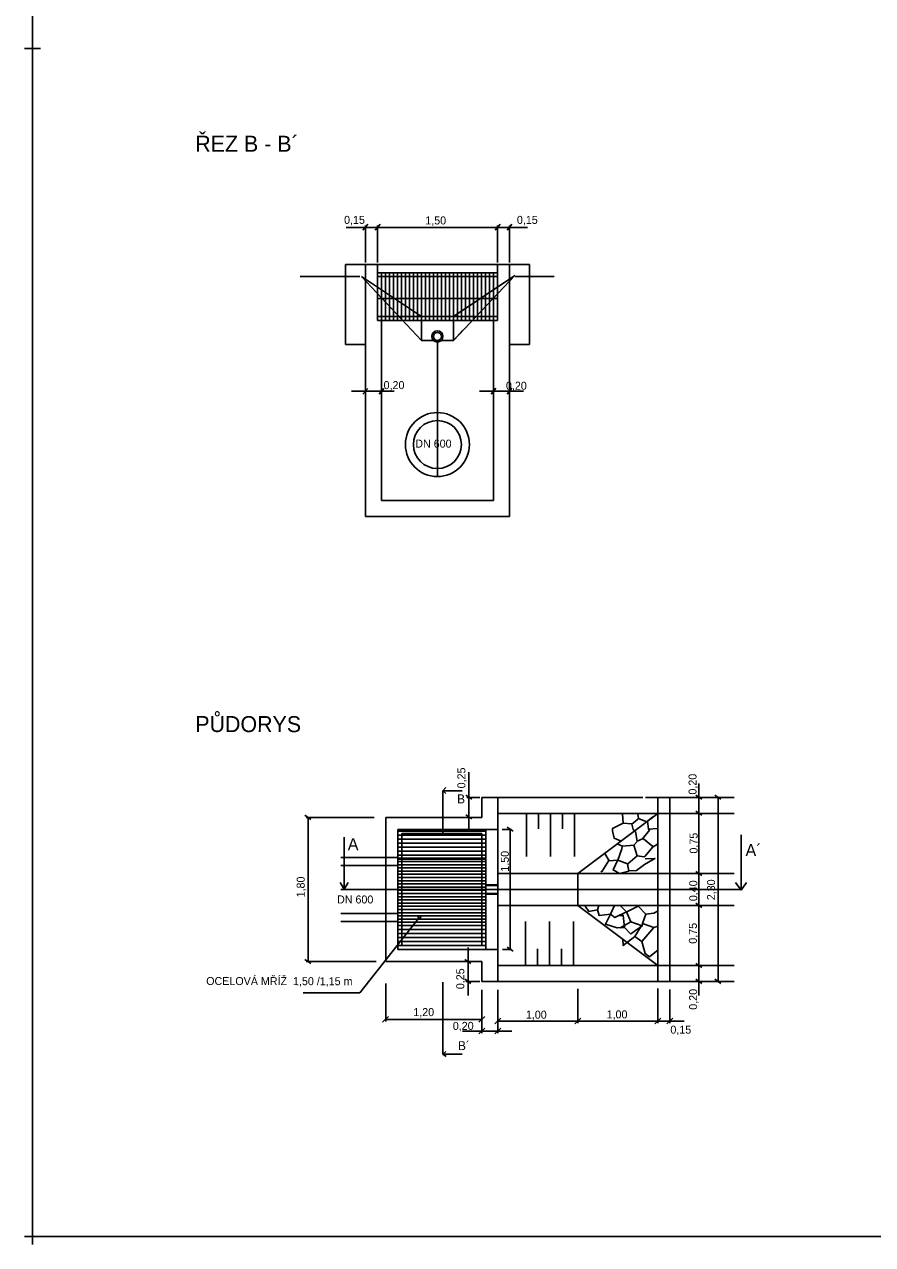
# Model space of a CAD drawing. Extents: x -463166.8 to -463145.6, y -1105023 to -1104993.1.
# Drawn here: x -463166.78 to -463156.18, y -1105022.98 to -1105007.73 of the extents above; entities that cross this region are included whole.
import ezdxf

# ---------------------------------------------------------------- set-up
doc = ezdxf.new("R2010")
doc.units = 0
doc.layers.add('Vrstva 14', color=7, linetype='Continuous')
doc.layers.add('Vrstva 57', color=7, linetype='Continuous')

msp = doc.modelspace()

# ---------------------------------------------------------------- linework, layer by layer
at = {"layer": 'Vrstva 14'}
for p, q in [((-463166.676, -1105007.928), (-463166.676, -1105008.128)), ((-463166.676, -1105007.928), (-463166.676, -1105008.128)), ((-463166.676, -1105007.928), (-463166.676, -1105008.128)), ((-463166.676, -1105007.928), (-463166.676, -1105008.128)), ((-463166.776, -1105008.028), (-463166.576, -1105008.028)), ((-463166.776, -1105008.028), (-463166.576, -1105008.028)), ((-463166.776, -1105008.028), (-463166.576, -1105008.028)), ((-463166.776, -1105008.028), (-463166.576, -1105008.028)), ((-463162.755, -1105010.265), (-463162.363, -1105010.265)), ((-463162.485, -1105010.226), (-463162.545, -1105010.3)), ((-463162.515, -1105010.365), (-463162.515, -1105010.24)), ((-463162.332, -1105010.226), (-463162.392, -1105010.3)), ((-463162.365, -1105010.703), (-463162.365, -1105010.24)), ((-463162.365, -1105010.487), (-463162.365, -1105010.241)), ((-463162.365, -1105010.266), (-463160.865, -1105010.266)), ((-463161.04, -1105010.265), (-463160.487, -1105010.265)), ((-463160.832, -1105010.226), (-463160.892, -1105010.3)), ((-463160.865, -1105010.365), (-463160.865, -1105010.24)), ((-463160.865, -1105010.487), (-463160.865, -1105010.241)), ((-463160.684, -1105010.226), (-463160.744, -1105010.3)), ((-463160.715, -1105010.703), (-463160.715, -1105010.24)), ((-463162.515, -1105010.703), (-463162.515, -1105010.365)), ((-463160.865, -1105010.703), (-463160.865, -1105010.365)), ((-463162.765, -1105010.728), (-463162.765, -1105011.728)), ((-463162.515, -1105010.728), (-463162.765, -1105010.728)), ((-463162.515, -1105010.728), (-463162.365, -1105010.728)), ((-463162.515, -1105010.728), (-463162.515, -1105011.972)), ((-463162.365, -1105010.728), (-463160.865, -1105010.728)), ((-463162.365, -1105010.728), (-463162.365, -1105011.153)), ((-463160.865, -1105010.728), (-463160.715, -1105010.728)), ((-463160.865, -1105010.728), (-463160.865, -1105011.153)), ((-463160.715, -1105010.728), (-463160.465, -1105010.728)), ((-463160.715, -1105010.728), (-463160.715, -1105011.972)), ((-463160.465, -1105010.728), (-463160.465, -1105011.728)), ((-463163.331, -1105010.878), (-463162.583, -1105010.878)), ((-463162.565, -1105010.878), (-463161.828, -1105011.37)), ((-463162.565, -1105010.878), (-463161.815, -1105011.678)), ((-463162.365, -1105010.832), (-463160.865, -1105010.832)), ((-463162.365, -1105011.428), (-463162.365, -1105010.878)), ((-463162.365, -1105010.878), (-463160.865, -1105010.878)), ((-463162.315, -1105011.431), (-463162.315, -1105010.832)), ((-463162.265, -1105011.431), (-463162.265, -1105010.832)), ((-463162.215, -1105011.431), (-463162.215, -1105010.832)), ((-463162.165, -1105011.431), (-463162.165, -1105010.832)), ((-463162.115, -1105011.431), (-463162.115, -1105010.832)), ((-463162.065, -1105011.431), (-463162.065, -1105010.832)), ((-463162.015, -1105011.431), (-463162.015, -1105010.832)), ((-463161.965, -1105011.431), (-463161.965, -1105010.832)), ((-463161.915, -1105011.431), (-463161.915, -1105010.832)), ((-463161.865, -1105011.431), (-463161.865, -1105010.832)), ((-463161.815, -1105011.431), (-463161.815, -1105010.832)), ((-463161.765, -1105011.431), (-463161.765, -1105010.832)), ((-463161.715, -1105011.431), (-463161.715, -1105010.832)), ((-463161.665, -1105011.431), (-463161.665, -1105010.832)), ((-463161.615, -1105011.431), (-463161.615, -1105010.832)), ((-463161.565, -1105011.32), (-463161.565, -1105010.832)), ((-463161.515, -1105011.318), (-463161.515, -1105010.832)), ((-463161.465, -1105011.317), (-463161.465, -1105010.832)), ((-463161.465, -1105011.317), (-463161.465, -1105010.832)), ((-463161.415, -1105011.315), (-463161.415, -1105010.832)), ((-463161.415, -1105011.378), (-463160.648, -1105010.867)), ((-463161.415, -1105011.678), (-463160.648, -1105010.867)), ((-463161.365, -1105011.314), (-463161.365, -1105010.832)), ((-463161.315, -1105011.428), (-463161.315, -1105010.832)), ((-463161.265, -1105011.428), (-463161.265, -1105010.832)), ((-463161.265, -1105011.311), (-463161.265, -1105010.878)), ((-463161.215, -1105011.428), (-463161.215, -1105010.832)), ((-463161.215, -1105011.309), (-463161.215, -1105010.878)), ((-463161.165, -1105011.428), (-463161.165, -1105010.832)), ((-463161.115, -1105011.428), (-463161.115, -1105010.832)), ((-463161.065, -1105011.428), (-463161.065, -1105010.832)), ((-463161.015, -1105011.431), (-463161.015, -1105010.832)), ((-463160.965, -1105011.431), (-463160.965, -1105010.832)), ((-463160.915, -1105011.431), (-463160.915, -1105010.832)), ((-463160.865, -1105011.428), (-463160.865, -1105010.878)), ((-463160.641, -1105010.878), (-463160.157, -1105010.878)), ((-463162.315, -1105011.153), (-463162.365, -1105011.153)), ((-463160.915, -1105011.153), (-463162.365, -1105011.153)), ((-463162.315, -1105011.153), (-463162.315, -1105011.428)), ((-463162.123, -1105011.153), (-463162.315, -1105011.153)), ((-463160.865, -1105011.153), (-463160.915, -1105011.153)), ((-463160.915, -1105011.153), (-463160.915, -1105011.972)), ((-463161.865, -1105011.431), (-463161.865, -1105011.32)), ((-463161.815, -1105011.431), (-463161.815, -1105011.318)), ((-463161.765, -1105011.431), (-463161.765, -1105011.317)), ((-463161.765, -1105011.431), (-463161.765, -1105011.317)), ((-463161.715, -1105011.431), (-463161.715, -1105011.315)), ((-463161.665, -1105011.431), (-463161.665, -1105011.314)), ((-463161.615, -1105011.431), (-463161.615, -1105011.312)), ((-463161.565, -1105011.431), (-463161.565, -1105011.311)), ((-463161.565, -1105011.431), (-463161.565, -1105011.311)), ((-463161.515, -1105011.431), (-463161.515, -1105011.309)), ((-463161.515, -1105011.431), (-463161.515, -1105011.309)), ((-463161.465, -1105011.431), (-463161.465, -1105011.308)), ((-463161.415, -1105011.431), (-463161.415, -1105011.306)), ((-463161.415, -1105011.378), (-463161.331, -1105011.322)), ((-463161.365, -1105011.431), (-463161.365, -1105011.305)), ((-463162.365, -1105011.378), (-463161.579, -1105011.378)), ((-463162.365, -1105011.428), (-463161.577, -1105011.428)), ((-463162.315, -1105011.428), (-463162.315, -1105011.972)), ((-463161.879, -1105011.378), (-463160.865, -1105011.378)), ((-463161.877, -1105011.428), (-463160.865, -1105011.428)), ((-463161.828, -1105011.37), (-463161.815, -1105011.378)), ((-463161.815, -1105011.378), (-463161.828, -1105011.37)), ((-463161.815, -1105011.678), (-463161.815, -1105011.378)), ((-463161.415, -1105011.678), (-463161.415, -1105011.378)), ((-463161.834, -1105011.658), (-463161.815, -1105011.678)), ((-463161.415, -1105011.678), (-463161.299, -1105011.555)), ((-463162.515, -1105011.728), (-463162.765, -1105011.728)), ((-463161.815, -1105011.678), (-463161.415, -1105011.678)), ((-463161.615, -1105011.678), (-463161.615, -1105011.972)), ((-463160.715, -1105011.728), (-463160.465, -1105011.728)), ((-463162.515, -1105011.887), (-463162.515, -1105012.337)), ((-463162.315, -1105011.887), (-463162.315, -1105012.337)), ((-463160.915, -1105011.887), (-463160.915, -1105012.337)), ((-463160.715, -1105011.887), (-463160.715, -1105012.337)), ((-463162.515, -1105011.972), (-463162.515, -1105013.879)), ((-463162.515, -1105012.038), (-463162.515, -1105012.473)), ((-463162.315, -1105011.972), (-463162.315, -1105013.679)), ((-463162.315, -1105012.006), (-463162.315, -1105012.337)), ((-463161.615, -1105011.972), (-463161.615, -1105013.379)), ((-463160.915, -1105011.972), (-463160.915, -1105013.679)), ((-463160.915, -1105012.006), (-463160.915, -1105012.337)), ((-463160.715, -1105011.972), (-463160.715, -1105013.879)), ((-463160.715, -1105012.038), (-463160.715, -1105012.473)), ((-463162.156, -1105012.312), (-463162.69, -1105012.312)), ((-463162.485, -1105012.277), (-463162.545, -1105012.35)), ((-463162.284, -1105012.277), (-463162.344, -1105012.35)), ((-463162.315, -1105012.312), (-463162.156, -1105012.312)), ((-463161.09, -1105012.312), (-463160.915, -1105012.312)), ((-463161.022, -1105012.312), (-463160.915, -1105012.312)), ((-463160.884, -1105012.274), (-463160.944, -1105012.348)), ((-463160.715, -1105012.312), (-463160.915, -1105012.312)), ((-463160.684, -1105012.274), (-463160.744, -1105012.348)), ((-463160.54, -1105012.312), (-463160.715, -1105012.312)), ((-463162.315, -1105013.679), (-463160.915, -1105013.679)), ((-463162.515, -1105013.879), (-463160.715, -1105013.879)), ((-463161.221, -1105017.072), (-463161.221, -1105017.39)), ((-463161.548, -1105017.306), (-463161.509, -1105017.264)), ((-463158.346, -1105017.215), (-463158.346, -1105017.39)), ((-463161.51, -1105017.342), (-463161.548, -1105017.306)), ((-463161.547, -1105017.306), (-463161.547, -1105017.835)), ((-463161.306, -1105017.306), (-463161.547, -1105017.306)), ((-463161.186, -1105017.412), (-463161.259, -1105017.361)), ((-463161.086, -1105017.39), (-463161.246, -1105017.39)), ((-463161.221, -1105017.64), (-463161.221, -1105017.39)), ((-463161.061, -1105017.39), (-463161.061, -1105017.64)), ((-463161.061, -1105017.39), (-463159.047, -1105017.39)), ((-463160.861, -1105017.39), (-463160.861, -1105019.69)), ((-463159.013, -1105017.39), (-463158.321, -1105017.39)), ((-463158.861, -1105017.39), (-463158.861, -1105018.34)), ((-463158.861, -1105017.39), (-463158.711, -1105017.39)), ((-463158.711, -1105017.39), (-463158.711, -1105019.69)), ((-463158.585, -1105017.39), (-463157.907, -1105017.39)), ((-463158.483, -1105017.39), (-463158.082, -1105017.39)), ((-463158.311, -1105017.412), (-463158.384, -1105017.361)), ((-463158.346, -1105017.39), (-463158.346, -1105017.59)), ((-463158.073, -1105017.412), (-463158.147, -1105017.361)), ((-463158.107, -1105017.39), (-463158.107, -1105019.69)), ((-463161.186, -1105017.659), (-463161.259, -1105017.608)), ((-463160.861, -1105017.59), (-463158.861, -1105017.59)), ((-463160.502, -1105018.127), (-463160.502, -1105017.59)), ((-463160.352, -1105017.783), (-463160.352, -1105017.59)), ((-463160.202, -1105018.127), (-463160.202, -1105017.59)), ((-463160.052, -1105017.783), (-463160.052, -1105017.59)), ((-463159.902, -1105018.127), (-463159.902, -1105017.59)), ((-463159.861, -1105018.34), (-463158.861, -1105017.59)), ((-463159.013, -1105017.59), (-463158.321, -1105017.59)), ((-463158.861, -1105017.59), (-463157.907, -1105017.59)), ((-463158.311, -1105017.612), (-463158.384, -1105017.561)), ((-463158.346, -1105017.765), (-463158.346, -1105017.59)), ((-463158.346, -1105017.59), (-463158.346, -1105018.34)), ((-463163.197, -1105017.665), (-463163.27, -1105017.613)), ((-463162.406, -1105017.64), (-463163.256, -1105017.64)), ((-463163.231, -1105017.64), (-463163.231, -1105019.44)), ((-463162.261, -1105017.64), (-463161.061, -1105017.64)), ((-463162.261, -1105017.64), (-463162.261, -1105019.44)), ((-463161.086, -1105017.64), (-463161.246, -1105017.64)), ((-463161.221, -1105017.815), (-463161.221, -1105017.64)), ((-463160.668, -1105017.812), (-463160.742, -1105017.761)), ((-463162.78, -1105017.887), (-463162.78, -1105018.534)), ((-463162.111, -1105017.79), (-463162.111, -1105019.29)), ((-463162.111, -1105017.79), (-463160.861, -1105017.79)), ((-463162.111, -1105017.79), (-463160.861, -1105017.79)), ((-463162.111, -1105017.81), (-463161.011, -1105017.81)), ((-463162.111, -1105017.86), (-463161.011, -1105017.86)), ((-463162.111, -1105017.91), (-463161.011, -1105017.91)), ((-463162.086, -1105017.79), (-463161.848, -1105017.79)), ((-463162.061, -1105017.84), (-463162.061, -1105019.24)), ((-463162.061, -1105017.84), (-463161.061, -1105017.84)), ((-463161.061, -1105017.84), (-463161.061, -1105019.24)), ((-463161.011, -1105017.79), (-463161.011, -1105019.29)), ((-463160.69, -1105017.791), (-463160.805, -1105017.791)), ((-463160.704, -1105019.29), (-463160.704, -1105017.79)), ((-463157.82, -1105017.859), (-463157.82, -1105018.55)), ((-463162.111, -1105017.96), (-463161.011, -1105017.96)), ((-463162.111, -1105018.01), (-463161.011, -1105018.01)), ((-463162.111, -1105018.06), (-463161.011, -1105018.06)), ((-463162.822, -1105018.14), (-463162.261, -1105018.14)), ((-463162.261, -1105018.14), (-463162.111, -1105018.14)), ((-463162.111, -1105018.11), (-463161.011, -1105018.11)), ((-463162.111, -1105018.15), (-463161.011, -1105018.15)), ((-463162.111, -1105018.16), (-463161.011, -1105018.16)), ((-463162.111, -1105018.19), (-463161.011, -1105018.19)), ((-463158.346, -1105018.165), (-463158.346, -1105018.34)), ((-463162.822, -1105018.24), (-463162.261, -1105018.24)), ((-463162.261, -1105018.24), (-463162.111, -1105018.24)), ((-463162.111, -1105018.23), (-463161.011, -1105018.23)), ((-463162.111, -1105018.27), (-463161.011, -1105018.27)), ((-463162.111, -1105018.31), (-463161.011, -1105018.31)), ((-463162.111, -1105018.35), (-463161.011, -1105018.35)), ((-463160.861, -1105018.34), (-463157.907, -1105018.34)), ((-463159.861, -1105018.34), (-463159.861, -1105018.74)), ((-463159.013, -1105018.34), (-463158.321, -1105018.34)), ((-463158.861, -1105018.34), (-463158.861, -1105018.74)), ((-463158.311, -1105018.367), (-463158.384, -1105018.316)), ((-463158.346, -1105018.34), (-463158.346, -1105018.74)), ((-463162.78, -1105018.534), (-463162.831, -1105018.451)), ((-463162.78, -1105018.534), (-463162.729, -1105018.451)), ((-463162.111, -1105018.39), (-463161.011, -1105018.39)), ((-463162.111, -1105018.43), (-463161.011, -1105018.43)), ((-463162.111, -1105018.47), (-463162.024, -1105018.47)), ((-463162.111, -1105018.51), (-463162.027, -1105018.51)), ((-463162.061, -1105018.47), (-463161.011, -1105018.47)), ((-463162.061, -1105018.51), (-463161.011, -1105018.51)), ((-463161.011, -1105018.48), (-463160.861, -1105018.48)), ((-463161.011, -1105018.49), (-463160.861, -1105018.49)), ((-463157.888, -1105018.452), (-463157.819, -1105018.55)), ((-463157.751, -1105018.452), (-463157.82, -1105018.55)), ((-463162.822, -1105018.54), (-463157.809, -1105018.54)), ((-463162.111, -1105018.55), (-463162.027, -1105018.55)), ((-463162.111, -1105018.59), (-463162.027, -1105018.59)), ((-463162.111, -1105018.63), (-463161.011, -1105018.63)), ((-463162.111, -1105018.67), (-463161.011, -1105018.67)), ((-463162.061, -1105018.55), (-463161.011, -1105018.55)), ((-463162.027, -1105018.59), (-463161.011, -1105018.59)), ((-463161.011, -1105018.59), (-463160.861, -1105018.59)), ((-463161.011, -1105018.6), (-463160.861, -1105018.6)), ((-463162.111, -1105018.71), (-463161.011, -1105018.71)), ((-463162.111, -1105018.75), (-463161.011, -1105018.75)), ((-463162.111, -1105018.79), (-463161.011, -1105018.79)), ((-463160.861, -1105018.74), (-463157.907, -1105018.74)), ((-463159.861, -1105018.74), (-463158.861, -1105019.49)), ((-463159.013, -1105018.74), (-463158.321, -1105018.74)), ((-463158.861, -1105018.74), (-463158.861, -1105019.69)), ((-463158.311, -1105018.765), (-463158.384, -1105018.713)), ((-463158.346, -1105018.915), (-463158.346, -1105018.74)), ((-463158.346, -1105018.74), (-463158.346, -1105019.49)), ((-463162.822, -1105018.84), (-463162.261, -1105018.84)), ((-463162.822, -1105018.94), (-463162.261, -1105018.94)), ((-463162.584, -1105019.831), (-463161.839, -1105018.887)), ((-463162.261, -1105018.84), (-463162.111, -1105018.84)), ((-463162.261, -1105018.94), (-463162.111, -1105018.94)), ((-463162.111, -1105018.83), (-463161.011, -1105018.83)), ((-463162.111, -1105018.87), (-463161.011, -1105018.87)), ((-463162.111, -1105018.91), (-463161.011, -1105018.91)), ((-463162.111, -1105018.95), (-463161.011, -1105018.95)), ((-463160.512, -1105018.939), (-463160.512, -1105019.476)), ((-463160.212, -1105018.939), (-463160.212, -1105019.476)), ((-463159.912, -1105018.939), (-463159.912, -1105019.476)), ((-463162.111, -1105018.99), (-463161.011, -1105018.99)), ((-463162.111, -1105019.04), (-463161.011, -1105019.04)), ((-463162.111, -1105019.09), (-463161.011, -1105019.09)), ((-463162.111, -1105019.14), (-463161.011, -1105019.14)), ((-463162.111, -1105019.19), (-463161.011, -1105019.19)), ((-463162.111, -1105019.24), (-463161.011, -1105019.24)), ((-463162.061, -1105019.24), (-463161.061, -1105019.24)), ((-463161.23, -1105019.265), (-463161.23, -1105019.44)), ((-463160.668, -1105019.312), (-463160.742, -1105019.261)), ((-463160.362, -1105019.283), (-463160.362, -1105019.476)), ((-463160.062, -1105019.283), (-463160.062, -1105019.476)), ((-463163.197, -1105019.465), (-463163.27, -1105019.414)), ((-463162.111, -1105019.29), (-463160.861, -1105019.29)), ((-463162.111, -1105019.29), (-463160.861, -1105019.29)), ((-463162.086, -1105019.29), (-463161.848, -1105019.29)), ((-463161.196, -1105019.466), (-463161.27, -1105019.414)), ((-463160.802, -1105019.29), (-463160.687, -1105019.29)), ((-463158.346, -1105019.315), (-463158.346, -1105019.49)), ((-463162.38, -1105019.44), (-463163.256, -1105019.44)), ((-463162.261, -1105019.44), (-463161.061, -1105019.44)), ((-463161.086, -1105019.44), (-463161.255, -1105019.44)), ((-463161.23, -1105019.44), (-463161.23, -1105019.69)), ((-463161.061, -1105019.44), (-463161.061, -1105019.69)), ((-463160.861, -1105019.49), (-463158.861, -1105019.49)), ((-463159.013, -1105019.49), (-463158.321, -1105019.49)), ((-463159.013, -1105019.49), (-463158.321, -1105019.49)), ((-463158.648, -1105019.49), (-463157.907, -1105019.49)), ((-463158.311, -1105019.515), (-463158.384, -1105019.464)), ((-463158.346, -1105019.49), (-463158.346, -1105019.69)), ((-463162.261, -1105019.715), (-463162.261, -1105020.188)), ((-463161.547, -1105019.697), (-463161.547, -1105020.598)), ((-463161.196, -1105019.714), (-463161.27, -1105019.663)), ((-463161.086, -1105019.69), (-463161.255, -1105019.69)), ((-463161.23, -1105019.865), (-463161.23, -1105019.69)), ((-463161.061, -1105019.69), (-463159.013, -1105019.69)), ((-463159.013, -1105019.69), (-463158.321, -1105019.69)), ((-463158.861, -1105019.69), (-463158.711, -1105019.69)), ((-463158.619, -1105019.69), (-463158.597, -1105019.69)), ((-463158.483, -1105019.69), (-463158.082, -1105019.69)), ((-463158.311, -1105019.714), (-463158.384, -1105019.663)), ((-463158.346, -1105019.865), (-463158.346, -1105019.69)), ((-463158.073, -1105019.714), (-463158.147, -1105019.662)), ((-463158.082, -1105019.69), (-463157.907, -1105019.69)), ((-463162.584, -1105019.831), (-463163.294, -1105019.831)), ((-463161.061, -1105019.795), (-463161.061, -1105020.334)), ((-463160.861, -1105019.793), (-463160.861, -1105020.209)), ((-463159.861, -1105019.78), (-463159.861, -1105020.209)), ((-463158.861, -1105019.776), (-463158.861, -1105020.209)), ((-463158.711, -1105019.788), (-463158.711, -1105020.209)), ((-463162.299, -1105020.199), (-463162.225, -1105020.128)), ((-463161.061, -1105020.163), (-463162.261, -1105020.163)), ((-463161.097, -1105020.199), (-463161.024, -1105020.128)), ((-463160.896, -1105020.219), (-463160.822, -1105020.148)), ((-463159.861, -1105020.184), (-463160.861, -1105020.184)), ((-463159.896, -1105020.219), (-463159.823, -1105020.148)), ((-463158.861, -1105020.184), (-463159.861, -1105020.184)), ((-463159.036, -1105020.184), (-463158.861, -1105020.184)), ((-463158.897, -1105020.219), (-463158.823, -1105020.148)), ((-463158.711, -1105020.184), (-463158.861, -1105020.184)), ((-463158.746, -1105020.219), (-463158.673, -1105020.148)), ((-463158.532, -1105020.184), (-463158.711, -1105020.184)), ((-463161.303, -1105020.309), (-463161.061, -1105020.309)), ((-463161.097, -1105020.344), (-463161.024, -1105020.273)), ((-463160.861, -1105020.309), (-463161.061, -1105020.309)), ((-463160.896, -1105020.344), (-463160.823, -1105020.273)), ((-463160.861, -1105020.209), (-463160.861, -1105020.334)), ((-463160.686, -1105020.309), (-463160.861, -1105020.309)), ((-463161.547, -1105020.598), (-463161.511, -1105020.564)), ((-463161.306, -1105020.598), (-463161.547, -1105020.598)), ((-463161.547, -1105020.598), (-463161.504, -1105020.629)), ((-463166.676, -1105022.778), (-463166.676, -1105022.978)), ((-463166.676, -1105022.778), (-463166.676, -1105022.978)), ((-463166.776, -1105022.878), (-463166.576, -1105022.878)), ((-463166.776, -1105022.878), (-463166.576, -1105022.878))]:
    msp.add_line(p, q, dxfattribs=at)
msp.add_lwpolyline([(-463166.676, -1104993.178), (-463145.676, -1104993.178), (-463145.676, -1105022.878), (-463166.676, -1105022.878)], close=True, dxfattribs=at)
for points in [[(-463159.19, -1105017.72), (-463159.293, -1105017.711), (-463159.302, -1105017.598)], [(-463158.987, -1105017.697), (-463159.1, -1105017.652), (-463159.109, -1105017.598)], [(-463159.293, -1105017.711), (-463159.428, -1105017.778), (-463159.428, -1105017.806), (-463159.406, -1105017.9), (-463159.32, -1105017.936)], [(-463159.095, -1105017.648), (-463159.185, -1105017.724), (-463159.167, -1105017.792), (-463159.149, -1105017.806)], [(-463158.866, -1105017.778), (-463158.978, -1105017.787), (-463158.987, -1105017.688), (-463158.924, -1105017.63)], [(-463159.14, -1105017.815), (-463159.118, -1105017.936), (-463159.05, -1105017.909), (-463158.965, -1105017.797), (-463158.974, -1105017.783)], [(-463159.041, -1105017.909), (-463158.924, -1105018.004), (-463158.92, -1105018.008), (-463158.866, -1105017.972)], [(-463159.158, -1105017.986), (-463159.302, -1105017.999), (-463159.361, -1105017.972)], [(-463159.118, -1105018.121), (-463159.235, -1105018.22), (-463159.239, -1105018.22), (-463159.361, -1105018.175), (-463159.311, -1105018.031), (-463159.307, -1105018.004)], [(-463158.924, -1105018.008), (-463159.019, -1105018.125), (-463159.032, -1105018.13), (-463159.118, -1105018.121), (-463159.158, -1105017.986), (-463159.113, -1105017.936)], [(-463159.473, -1105018.179), (-463159.554, -1105018.31), (-463159.572, -1105018.319)], [(-463159.361, -1105018.175), (-463159.469, -1105018.184), (-463159.523, -1105018.089)], [(-463159.361, -1105018.17), (-463159.419, -1105018.296), (-463159.338, -1105018.341), (-463159.221, -1105018.31), (-463159.239, -1105018.22)], [(-463159.226, -1105018.305), (-463159.127, -1105018.301), (-463159.028, -1105018.229), (-463158.897, -1105018.152), (-463159.019, -1105018.157)], [(-463159.613, -1105018.796), (-463159.721, -1105018.814), (-463159.77, -1105018.747)], [(-463159.451, -1105018.85), (-463159.595, -1105018.864), (-463159.613, -1105018.796), (-463159.599, -1105018.742)], [(-463159.253, -1105018.819), (-463159.397, -1105018.891), (-463159.451, -1105018.85), (-463159.401, -1105018.742)], [(-463159.253, -1105018.819), (-463159.329, -1105018.742)], [(-463159.104, -1105018.747), (-463159.239, -1105018.814), (-463159.253, -1105018.819), (-463159.199, -1105018.945), (-463159.055, -1105018.994), (-463159.05, -1105018.958)], [(-463159.104, -1105018.747), (-463159.01, -1105018.85), (-463158.911, -1105018.837), (-463158.857, -1105018.805)], [(-463159.451, -1105018.85), (-463159.514, -1105018.972), (-463159.37, -1105019.021), (-463159.365, -1105019.021), (-463159.275, -1105019.017), (-463159.293, -1105018.864), (-463159.338, -1105018.864)], [(-463159.199, -1105018.945), (-463159.329, -1105019.021), (-463159.275, -1105019.017)], [(-463159.01, -1105018.85), (-463159.05, -1105018.967), (-463158.911, -1105019.017), (-463158.857, -1105018.999)], [(-463159.149, -1105019.129), (-463159.293, -1105019.242), (-463159.298, -1105019.161)], [(-463158.911, -1105019.017), (-463159.059, -1105019.192), (-463159.149, -1105019.129), (-463159.068, -1105018.999), (-463159.055, -1105018.994), (-463159.185, -1105019.084), (-463159.199, -1105019.098), (-463159.275, -1105019.017)], [(-463159.059, -1105019.192), (-463159.019, -1105019.341), (-463158.965, -1105019.381), (-463158.857, -1105019.296)]]:
    msp.add_lwpolyline(points, dxfattribs=at)
for centre, radius in [((-463161.615, -1105011.628), 0.07), ((-463161.615, -1105011.628), 0.05), ((-463161.615, -1105012.979), 0.4), ((-463161.615, -1105012.979), 0.3), ((-463161.839, -1105018.887), 0.0171)]:
    msp.add_circle(centre, radius, dxfattribs=at)

# ---------------------------------------------------------------- texts
for s, p in [('0,15', (-463162.781, -1105010.221)), ('1,50', (-463161.766, -1105010.228)), ('0,15', (-463160.621, -1105010.221)), ('0,20', (-463162.287, -1105012.286)), ('0,20', (-463160.758, -1105012.294)), ('1,20', (-463161.916, -1105020.123)), ('1,00', (-463159.5, -1105020.151)), ('0,20', (-463161.422, -1105020.295)), ('1,00', (-463160.509, -1105020.155)), ('0,15', (-463158.703, -1105020.342))]:
    msp.add_text(s, height=0.1, dxfattribs=at).set_placement(p)
for s, p in [('0,25', (-463161.265, -1105017.276)), ('0,20', (-463158.376, -1105017.354)), ('0,75', (-463158.363, -1105018.091)), ('1,50', (-463160.722, -1105018.318)), ('1,80', (-463163.273, -1105018.639)), ('0,40', (-463158.367, -1105018.686)), ('2,30', (-463158.145, -1105018.674)), ('0,75', (-463158.372, -1105019.218)), ('0,25', (-463161.279, -1105019.786)), ('0,20', (-463158.369, -1105020.043))]:
    msp.add_text(s, height=0.1, rotation=90, dxfattribs=at).set_placement(p)
at = {"layer": 'Vrstva 57'}
for s, height, rotation, p in [('ŘEZ B - B´', 0.2, 359.9224, (-463164.641, -1105009.318)), ('DN 600', 0.1, 359.903, (-463161.891, -1105013.017)), ('PŮDORYS', 0.2, 359.9224, (-463164.641, -1105016.572)), ('B', 0.112, 359.9224, (-463161.369, -1105017.464)), ('A', 0.15, 359.9224, (-463162.735, -1105018.049)), ('A´', 0.15, 359.9224, (-463157.764, -1105018.122)), ('DN 600', 0.1, 359.903, (-463162.869, -1105018.714)), ('OCELOVÁ MŘÍŽ  1,50 /1,15 m', 0.1, 359.903, (-463164.504, -1105019.734)), ('B´', 0.112, 359.9224, (-463161.358, -1105020.548))]:
    msp.add_text(s, height=height, rotation=rotation, dxfattribs=at).set_placement(p)

doc.saveas('drawing.dxf')
